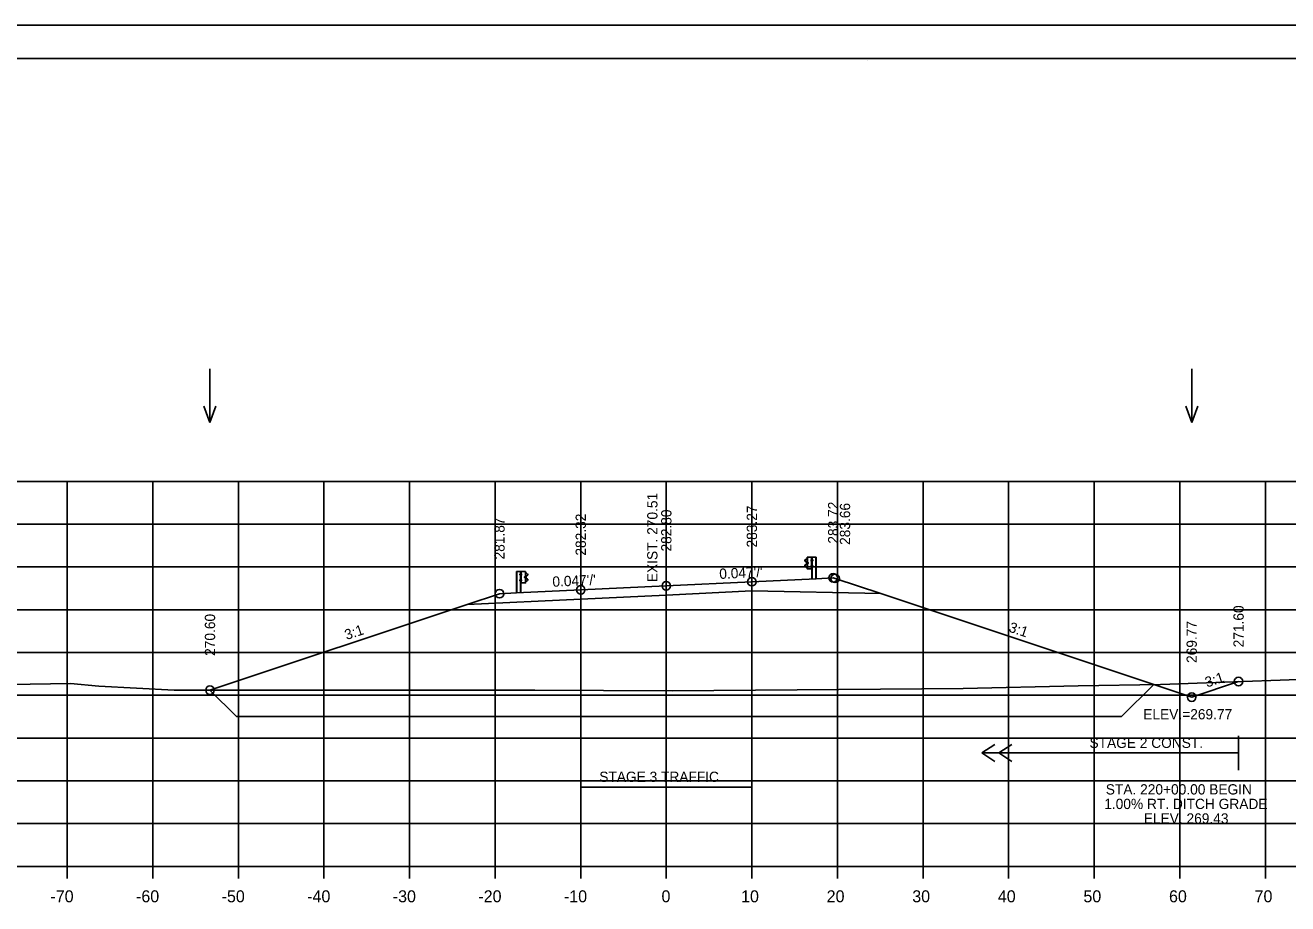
# Model space of a CAD drawing. Extents: x 4667 to 1632277, y -2100 to 724501.
# Drawn here: x 5702.3 to 5849.8, y -786.4 to -683.7 of the extents above; entities that cross this region are included whole.
import ezdxf

# ---------------------------------------------------------------- set-up
doc = ezdxf.new("R2010")
doc.units = 0
for name, color, linetype in [('R_Alt Surface', 7, 'Continuous'), ('R_Axis', 7, 'Continuous'), ('R_Axis Annot', 7, 'Continuous'), ('R_Border', 7, 'Continuous'), ('R_Draft', 7, 'Continuous'), ('R_Exist Surface', 7, 'Continuous'), ('R_Fin Surface', 7, 'Continuous'), ('R_Fin Surface Annot', 7, 'Continuous'), ('R_Grid', 7, 'Continuous'), ('R_No Plot', 7, 'Continuous'), ('R_Proposed CofA', 7, 'Continuous'), ('R_ROW', 7, 'Continuous'), ('R_Temp Easement', 7, 'Continuous'), ('R_Water Annot', 7, 'Continuous')]:
    doc.layers.add(name, color=color, linetype=linetype)

msp = doc.modelspace()

# ---------------------------------------------------------------- linework, layer by layer
at = {"layer": 'R_Alt Surface'}
msp.add_lwpolyline([(5753.9, -751.44), (5767.18, -750.81), (5777.18, -750.34), (5787.18, -749.86), (5802.24, -750.17)], dxfattribs=at)
at = {"layer": 'R_Axis'}
for p, q in [((5667.18, -782.05), (5947.18, -782.05)), ((5707.18, -783.45), (5707.18, -782.05)), ((5717.18, -783.45), (5717.18, -782.05)), ((5727.18, -783.45), (5727.18, -782.05)), ((5737.18, -783.45), (5737.18, -782.05)), ((5747.18, -783.45), (5747.18, -782.05)), ((5757.18, -783.45), (5757.18, -782.05)), ((5767.18, -783.45), (5767.18, -782.05)), ((5777.18, -783.45), (5777.18, -782.05)), ((5787.18, -783.45), (5787.18, -782.05)), ((5797.18, -783.45), (5797.18, -782.05)), ((5807.18, -783.45), (5807.18, -782.05)), ((5817.18, -783.45), (5817.18, -782.05)), ((5827.18, -783.45), (5827.18, -782.05)), ((5837.18, -783.45), (5837.18, -782.05)), ((5847.18, -783.45), (5847.18, -782.05))]:
    msp.add_line(p, q, dxfattribs=at)
at = {"layer": 'R_Border'}
for p, q in [((5648.18, -687.63), (5964.36, -687.63)), ((5800.7, -687.89), (5800.7, -687.89)), ((5800.7, -687.89), (5800.7, -687.89))]:
    msp.add_line(p, q, dxfattribs=at)
at = {"layer": 'R_Draft'}
for p, q in [((5793.39, -746.23), (5793.52, -746.13)), ((5793.56, -746.48), (5793.39, -746.37)), ((5793.4, -746.25), (5793.53, -746.14)), ((5793.57, -746.46), (5793.4, -746.35)), ((5793.52, -746.13), (5793.63, -746.07)), ((5793.53, -746.14), (5793.62, -746.09)), ((5793.66, -747.28), (5793.66, -745.92)), ((5794.15, -746.22), (5794.1, -746.22)), ((5794.1, -746.22), (5794.1, -746.34)), ((5794.1, -746.28), (5794.16, -746.28)), ((5794.15, -746.34), (5794.1, -746.34)), ((5794.16, -745.91), (5794.17, -745.91)), ((5794.16, -745.91), (5794.23, -745.91)), ((5794.19, -748.43), (5794.19, -745.91)), ((5794.23, -746.34), (5794.23, -746.21)), ((5794.23, -746.21), (5794.28, -746.21)), ((5794.23, -746.24), (5794.28, -746.24)), ((5794.23, -746.31), (5794.27, -746.31)), ((5794.23, -746.31), (5794.28, -746.31)), ((5794.23, -746.34), (5794.28, -746.34)), ((5794.28, -746.32), (5794.28, -746.23)), ((5794.65, -745.91), (5794.65, -748.43)), ((5794.68, -745.91), (5794.68, -748.43)), ((5759.68, -747.57), (5759.68, -750.08)), ((5759.71, -747.57), (5759.71, -750.08)), ((5760.08, -747.98), (5760.08, -747.88)), ((5760.14, -747.87), (5760.09, -747.87)), ((5760.14, -747.9), (5760.09, -747.9)), ((5760.21, -747.57), (5760.14, -747.57)), ((5760.14, -747.99), (5760.14, -747.87)), ((5760.18, -750.08), (5760.18, -747.57)), ((5760.21, -747.57), (5760.2, -747.57)), ((5760.22, -747.87), (5760.27, -747.87)), ((5760.27, -747.87), (5760.27, -748)), ((5760.71, -748.93), (5760.71, -747.57)), ((5760.85, -747.78), (5760.74, -747.72)), ((5760.84, -747.8), (5760.75, -747.75)), ((5760.97, -747.9), (5760.84, -747.8)), ((5760.98, -747.89), (5760.85, -747.78)), ((5793.51, -747.08), (5793.38, -746.97)), ((5793.52, -747.06), (5793.4, -746.95)), ((5793.41, -746.81), (5793.57, -746.71)), ((5793.42, -746.83), (5793.58, -746.73)), ((5793.62, -747.13), (5793.51, -747.08)), ((5793.63, -747.12), (5793.52, -747.06)), ((5793.6, -746.66), (5793.6, -746.53)), ((5793.62, -746.66), (5793.62, -746.53)), ((5793.67, -746.66), (5793.67, -746.53)), ((5793.67, -746.53), (5793.72, -746.53)), ((5793.67, -746.56), (5793.72, -746.56)), ((5793.67, -746.63), (5793.72, -746.63)), ((5793.67, -746.63), (5793.72, -746.63)), ((5793.67, -746.66), (5793.72, -746.66)), ((5793.73, -746.64), (5793.73, -746.55)), ((5794.1, -747.03), (5794.1, -746.9)), ((5794.1, -746.9), (5794.15, -746.9)), ((5794.1, -746.96), (5794.16, -746.96)), ((5794.1, -747.03), (5794.15, -747.03)), ((5794.16, -747.28), (5794.19, -747.28)), ((5794.24, -747.03), (5794.24, -746.9)), ((5794.24, -746.9), (5794.29, -746.9)), ((5794.24, -746.93), (5794.29, -746.93)), ((5794.24, -747), (5794.28, -747)), ((5794.24, -747), (5794.29, -747)), ((5794.24, -747.03), (5794.29, -747.03)), ((5794.29, -747.01), (5794.29, -746.92)), ((5760.07, -748.67), (5760.07, -748.57)), ((5760.13, -748.56), (5760.08, -748.56)), ((5760.13, -748.59), (5760.08, -748.59)), ((5760.13, -748.65), (5760.08, -748.65)), ((5760.13, -748.68), (5760.08, -748.68)), ((5760.14, -747.96), (5760.09, -747.96)), ((5760.14, -747.99), (5760.09, -747.99)), ((5760.13, -748.65), (5760.09, -748.65)), ((5760.14, -747.96), (5760.1, -747.96)), ((5760.13, -748.68), (5760.13, -748.56)), ((5760.21, -748.93), (5760.17, -748.93)), ((5760.26, -747.94), (5760.21, -747.94)), ((5760.26, -748.62), (5760.21, -748.62)), ((5760.22, -748), (5760.27, -748)), ((5760.27, -748.56), (5760.22, -748.56)), ((5760.27, -748.68), (5760.22, -748.68)), ((5760.27, -748.68), (5760.27, -748.56)), ((5760.64, -748.3), (5760.64, -748.2)), ((5760.7, -748.19), (5760.65, -748.19)), ((5760.7, -748.22), (5760.65, -748.22)), ((5760.7, -748.28), (5760.65, -748.28)), ((5760.7, -748.28), (5760.65, -748.28)), ((5760.7, -748.31), (5760.65, -748.31)), ((5760.7, -748.31), (5760.7, -748.19)), ((5760.74, -748.77), (5760.84, -748.72)), ((5760.74, -748.79), (5760.86, -748.73)), ((5760.75, -748.31), (5760.75, -748.18)), ((5760.77, -748.31), (5760.77, -748.18)), ((5760.79, -748.11), (5760.97, -748.01)), ((5760.94, -748.49), (5760.79, -748.39)), ((5760.96, -748.47), (5760.8, -748.37)), ((5760.81, -748.13), (5760.98, -748.03)), ((5760.84, -748.72), (5760.97, -748.61)), ((5760.86, -748.73), (5760.98, -748.62))]:
    msp.add_line(p, q, dxfattribs=at)
for points in [[(5793.63, -745.91), (5793.64, -747.28), (5794.16, -747.28), (5794.16, -745.91)], [(5794.1, -746.22), (5794.1, -746.34), (5794.16, -746.34), (5794.16, -746.22)], [(5794.23, -746.19), (5794.23, -746.36), (5794.22, -746.36), (5794.22, -746.19)], [(5794.29, -746.24), (5794.29, -746.31), (5794.31, -746.31), (5794.31, -746.24)], [(5760.08, -747.9), (5760.08, -747.96), (5760.06, -747.96), (5760.06, -747.9)], [(5760.14, -747.85), (5760.14, -748.02), (5760.15, -748.02), (5760.15, -747.85)], [(5760.73, -747.57), (5760.73, -748.93), (5760.21, -748.93), (5760.21, -747.57)], [(5760.26, -747.87), (5760.26, -748), (5760.21, -748), (5760.21, -747.87)], [(5793.67, -746.51), (5793.67, -746.68), (5793.66, -746.68), (5793.66, -746.51)], [(5793.73, -746.56), (5793.73, -746.63), (5793.76, -746.63), (5793.76, -746.56)], [(5794.1, -746.9), (5794.1, -747.03), (5794.16, -747.03), (5794.16, -746.9)], [(5794.24, -746.88), (5794.24, -747.05), (5794.23, -747.05), (5794.23, -746.88)], [(5794.3, -746.93), (5794.3, -747), (5794.32, -747), (5794.32, -746.93)], [(5760.07, -748.59), (5760.07, -748.65), (5760.05, -748.65), (5760.05, -748.59)], [(5760.13, -748.54), (5760.13, -748.71), (5760.14, -748.71), (5760.14, -748.54)], [(5760.26, -748.56), (5760.26, -748.68), (5760.21, -748.68), (5760.21, -748.56)], [(5760.64, -748.22), (5760.64, -748.28), (5760.61, -748.28), (5760.61, -748.22)], [(5760.69, -748.17), (5760.69, -748.34), (5760.7, -748.34), (5760.7, -748.17)]]:
    msp.add_lwpolyline(points, close=True, dxfattribs=at)
for points in [[(5794.68, -745.91), (5794.23, -745.91), (5794.23, -748.43)], [(5759.68, -747.57), (5760.14, -747.57), (5760.14, -750.08)]]:
    msp.add_lwpolyline(points, dxfattribs=at)
for centre, radius, start, end in [((5793.43, -746.3), 0.0856, 122.0217, 240.7501), ((5793.43, -746.3), 0.062, 122.0217, 240.7501), ((5794.26, -746.23), 0.022, 317.7756, 45.4255), ((5794.19, -746.27), 0.0922, 339.7423, 20.2577), ((5794.26, -746.32), 0.025, 323.3766, 39.0666), ((5760.11, -747.88), 0.022, 134.5745, 222.2244), ((5760.18, -747.93), 0.0922, 159.7423, 200.2577), ((5760.94, -747.95), 0.062, 299.2499, 57.9783), ((5760.94, -747.95), 0.0856, 299.2499, 57.9783), ((5793.47, -746.9), 0.109, 120.88, 214.7816), ((5793.47, -746.9), 0.0854, 120.88, 214.7816), ((5793.53, -746.53), 0.0622, 4.9556, 61.894), ((5793.6, -746.6), 0.0453, 93.9303, 257.0446), ((5793.53, -746.53), 0.0865, 4.9556, 61.894), ((5793.55, -746.67), 0.0462, 293.1464, 8.2196), ((5793.55, -746.67), 0.0703, 293.1464, 8.2196), ((5793.71, -746.55), 0.022, 317.7756, 45.4255), ((5793.64, -746.6), 0.0922, 339.7423, 20.2577), ((5793.7, -746.64), 0.025, 323.3766, 39.0666), ((5794.27, -746.92), 0.022, 317.7756, 45.4255), ((5794.2, -746.96), 0.0922, 339.7423, 20.2577), ((5794.27, -747.01), 0.025, 323.3766, 39.0666), ((5760.1, -748.57), 0.022, 134.5745, 222.2244), ((5760.17, -748.62), 0.0922, 159.7423, 200.2577), ((5760.1, -748.67), 0.025, 140.9334, 216.6234), ((5760.11, -747.98), 0.025, 140.9334, 216.6234), ((5760.66, -748.2), 0.022, 134.5745, 222.2244), ((5760.73, -748.25), 0.0922, 159.7423, 200.2577), ((5760.67, -748.3), 0.025, 140.9334, 216.6234), ((5760.84, -748.19), 0.0865, 118.106, 175.0444), ((5760.82, -748.32), 0.0703, 171.7804, 246.8536), ((5760.84, -748.19), 0.0622, 118.106, 175.0444), ((5760.77, -748.26), 0.0453, 282.9554, 86.0697), ((5760.82, -748.32), 0.0462, 171.7804, 246.8536), ((5760.9, -748.56), 0.0854, 325.2184, 59.12), ((5760.9, -748.56), 0.109, 325.2184, 59.12)]:
    msp.add_arc(centre, radius, start, end, dxfattribs=at)
at = {"layer": 'R_Exist Surface'}
msp.add_lwpolyline([(5667.18, -761.13), (5676.98, -761.17), (5707.56, -760.67), (5710.87, -760.98), (5719.67, -761.47), (5723.42, -761.45), (5752.25, -761.46), (5757.35, -761.47), (5761.83, -761.45), (5777.88, -761.54), (5802.2, -761.33), (5811.85, -761.25), (5825.32, -760.96), (5834.92, -760.78), (5858.55, -759.92)], dxfattribs=at)
at = {"layer": 'R_Fin Surface'}
msp.add_lwpolyline([(5723.86, -761.45), (5753.9, -751.44), (5757.68, -750.18), (5759.68, -750.08), (5767.18, -749.73), (5777.18, -749.25), (5787.18, -748.78), (5794.68, -748.43), (5796.68, -748.33), (5796.9, -748.39), (5802.24, -750.17), (5838.57, -762.28), (5844.05, -760.45)], dxfattribs=at)
at = {"layer": 'R_Grid'}
for p, q in [((5667.18, -737.05), (5947.18, -737.05)), ((5707.18, -782.05), (5707.18, -737.05)), ((5717.18, -782.05), (5717.18, -737.05)), ((5727.18, -782.05), (5727.18, -737.05)), ((5737.18, -782.05), (5737.18, -737.05)), ((5747.18, -782.05), (5747.18, -737.05)), ((5757.18, -782.05), (5757.18, -737.05)), ((5767.18, -782.05), (5767.18, -737.05)), ((5777.18, -782.05), (5777.18, -737.05)), ((5787.18, -782.05), (5787.18, -737.05)), ((5797.18, -782.05), (5797.18, -737.05)), ((5807.18, -782.05), (5807.18, -737.05)), ((5817.18, -782.05), (5817.18, -737.05)), ((5827.18, -782.05), (5827.18, -737.05)), ((5837.18, -782.05), (5837.18, -737.05)), ((5847.18, -782.05), (5847.18, -737.05)), ((5667.18, -742.05), (5947.18, -742.05)), ((5667.18, -747.05), (5947.18, -747.05)), ((5667.18, -752.05), (5947.18, -752.05)), ((5667.18, -757.05), (5947.18, -757.05)), ((5667.18, -762.05), (5947.18, -762.05)), ((5667.18, -767.05), (5947.18, -767.05)), ((5667.18, -772.05), (5947.18, -772.05)), ((5667.18, -777.05), (5947.18, -777.05)), ((5667.18, -782.05), (5947.18, -782.05))]:
    msp.add_line(p, q, dxfattribs=at)
at = {"layer": 'R_No Plot'}
msp.add_line((5635.78, -683.74), (5969.12, -683.74), dxfattribs=at)
for points in [[(5635.78, -683.74), (5969.12, -683.74), (5969.12, -897.08), (5635.78, -897.08)], [(5882.1, -687.63), (5901.72, -687.63), (5901.72, -697.51), (5917.84, -697.51), (5941.04, -697.51), (5941.04, -721.84), (5964.36, -721.84), (5964.36, -893.09), (5648.18, -893.09), (5648.18, -687.63)]]:
    msp.add_lwpolyline(points, close=True, dxfattribs=at)
for centre in [(5796.68, -748.33), (5796.9, -748.39), (5767.18, -749.73), (5777.18, -749.25), (5787.18, -748.78), (5757.68, -750.18), (5757.68, -750.18), (5723.86, -761.45), (5844.05, -760.45), (5838.57, -762.28)]:
    msp.add_circle(centre, 0.5, dxfattribs=at)
at = {"layer": 'R_Proposed CofA'}
for p, q in [((5814.05, -768.79), (5815.55, -767.79)), ((5816.05, -768.79), (5817.55, -767.79)), ((5814.05, -768.79), (5815.55, -769.79)), ((5816.05, -768.79), (5817.55, -769.79))]:
    msp.add_line(p, q, dxfattribs=at)
at = {"layer": 'R_ROW'}
for p, q in [((5834.13, -760.8), (5830.38, -764.55)), ((5723.86, -761.45), (5726.95, -764.55)), ((5830.38, -764.55), (5726.95, -764.55))]:
    msp.add_line(p, q, dxfattribs=at)
at = {"layer": 'R_Temp Easement'}
for p, q in [((5844.05, -770.79), (5844.05, -766.79)), ((5844.05, -768.79), (5814.05, -768.79)), ((5767.18, -774.79), (5767.18, -770.79)), ((5787.18, -774.79), (5787.18, -770.79)), ((5787.18, -772.79), (5767.18, -772.79))]:
    msp.add_line(p, q, dxfattribs=at)
at = {"layer": 'R_Water Annot'}
for p, q in [((5723.86, -723.91), (5723.86, -730.19)), ((5838.57, -723.91), (5838.57, -730.19)), ((5723.86, -730.19), (5723.16, -728.27)), ((5723.86, -730.19), (5724.56, -728.27)), ((5838.57, -730.19), (5837.87, -728.27)), ((5838.57, -730.19), (5839.27, -728.27))]:
    msp.add_line(p, q, dxfattribs=at)

# ---------------------------------------------------------------- texts
at = {"layer": 'R_Axis Annot'}
for s, p in [('-70', (5705.22, -786.25)), ('-60', (5715.22, -786.25)), ('-50', (5725.22, -786.25)), ('-40', (5735.22, -786.25)), ('-30', (5745.22, -786.25)), ('-20', (5755.22, -786.25)), ('-10', (5765.22, -786.25)), ('0', (5776.62, -786.25)), ('10', (5785.92, -786.25)), ('20', (5795.92, -786.25)), ('30', (5805.92, -786.25)), ('40', (5815.92, -786.25)), ('50', (5825.92, -786.25)), ('60', (5835.92, -786.25)), ('70', (5845.92, -786.25))]:
    msp.add_text(s, height=1.4, dxfattribs=at).set_placement(p)
at = {"layer": 'R_Fin Surface Annot'}
for s, rotation, p in [('282.80', 90, (5777.78, -745.25)), ('283.27', 90, (5787.78, -744.78)), ('283.72', 90, (5797.28, -744.33)), ('283.66', 90, (5798.66, -744.48)), ('281.87', 90, (5758.28, -746.18)), ('282.32', 90, (5767.78, -745.73)), ("0.047'/'", 2.7085, (5763.9, -749.38)), ("0.047'/'", 2.7085, (5783.4, -748.46)), ('271.60', 90, (5844.65, -756.45)), ('270.60', 90, (5724.46, -757.45)), ('3:1', 341.5651, (5817.11, -754.59)), ('269.77', 90, (5839.17, -758.28)), ('3:1', 18.4349, (5739.82, -755.6)), ('3:1', 18.4349, (5840.36, -761.15))]:
    msp.add_text(s, height=1.2, rotation=rotation, dxfattribs=at).set_placement(p)
at = {"layer": 'R_Temp Easement'}
msp.add_text('EXIST. 270.51', height=1.2, rotation=90, dxfattribs=at).set_placement((5776.15, -748.83))
for s, p in [('STAGE 2 CONST.', (5826.63, -768.21)), ('STAGE 3 TRAFFIC', (5769.35, -772.18))]:
    msp.add_text(s, height=1.1985, dxfattribs=at).set_placement(p)
at = {"layer": 'R_Water Annot'}
for s, p in [('ELEV.=269.77', (5832.91, -764.87)), ('STA. 220+00.00 BEGIN', (5828.53, -773.65)), ('1.00% RT. DITCH GRADE', (5828.35, -775.35)), ('ELEV. 269.43', (5832.97, -777.05))]:
    msp.add_text(s, height=1.2, dxfattribs=at).set_placement(p)

doc.saveas('drawing.dxf')
